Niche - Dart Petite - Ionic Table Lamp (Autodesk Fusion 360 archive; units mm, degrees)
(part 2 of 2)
sketch "Sketch4" plane through (0, 23.8125, 0) normal (0, 1, 0) x axis (-1, 0, 0)
  line L1 (-7.1437, -2.6987) -> (-7.1437, 2.6987)
  line L2 (5.8737, -3.9688) -> (-5.8737, -3.9688)
  line L3 (7.1437, 2.6987) -> (7.1437, -2.6987)
  line L4 (-5.8737, 3.9688) -> (5.8737, 3.9688)
  line L5 (-3.81, 6.604) -> (3.81, 6.604)
  line L6 (3.81, -6.604) -> (-3.81, -6.604)
  line L7 (-10.414, 0) -> (10.414, 0)
  arc A1 centre (-5.8737, 2.6987) radius 1.27 clockwise from (-7.1437, 2.6987) to (-5.8737, 3.9688)
  arc A2 centre (-5.8737, -2.6987) radius 1.27 clockwise from (-5.8737, -3.9688) to (-7.1437, -2.6987)
  arc A3 centre (5.8737, -2.6987) radius 1.27 clockwise from (7.1437, -2.6987) to (5.8737, -3.9688)
  arc A4 centre (5.8737, 2.6987) radius 1.27 clockwise from (5.8737, 3.9688) to (7.1437, 2.6987)
  arc A5 centre (-3.81, 0) radius 6.604 clockwise from (-3.81, -6.604) to (-3.81, 6.604)
  arc A6 centre (3.81, 0) radius 6.604 clockwise from (3.81, 6.604) to (3.81, -6.604)
  point P20 (10.414, 0)
  point P21 (-10.414, 0)
  tangent L5 A5
  tangent A5 L6
  parallel L5 L6
  tangent L6 A6
  tangent L5 A6
  midpoint A6 P20
  midpoint A5 P21
  perpendicular L1 L7
extrude "Extrude4" add sketch "Sketch4" profile of A1 L1 A2 L2 A3 L3 A4 L4 L5 A5 L6 A6 against normal blind 2.286
chamfer "Chamfer2" distance 1.778
fillet "Fillet3" radius 1.778
fillet "Fillet4" radius 0.254
fillet "Fillet5" radius 0.254
fillet "Fillet6" radius 0.254
fillet "Fillet7" radius 3.175
sketch "Sketch5" plane through (0, 0, 0) normal (0, -1, 0) x axis (1, 0, 0)
  line L1 (-13.2397, -5.715) -> (-13.2397, 5.715)
  line L2 (9.6837, -9.271) -> (-9.6837, -9.271)
  line L3 (13.2397, 5.715) -> (13.2397, -5.715)
  line L4 (-9.6837, 9.271) -> (9.6837, 9.271)
  line L5 (-6.35, -3.175) -> (-6.35, 3.175)
  line L6 (6.35, 3.175) -> (-6.35, -3.175)
  line L7 (-6.35, 3.175) -> (6.35, -3.175)
  line L8 (-4.7625, 3.175) -> (-6.35, 3.175)
  line L9 (-4.7625, -3.175) -> (-4.7625, 3.175)
  line L10 (-6.35, -3.175) -> (-4.7625, -3.175)
  line L11 (-6.35, 3.175) -> (-6.35, -3.175)
  line L12 (0, -3.302) -> (0, 3.81)
  line L13 (4.7625, -3.175) -> (4.7625, 3.175)
  line L14 (4.7625, 3.175) -> (6.35, 3.175)
  line L15 (6.35, -3.175) -> (6.35, 3.175)
  line L16 (6.35, -3.175) -> (4.7625, -3.175)
  arc A1 centre (-9.6837, 5.715) radius 3.556 clockwise from (-13.2397, 5.715) to (-9.6837, 9.271)
  arc A2 centre (-9.6837, -5.715) radius 3.556 clockwise from (-9.6837, -9.271) to (-13.2397, -5.715)
  arc A3 centre (9.6837, -5.715) radius 3.556 clockwise from (13.2397, -5.715) to (9.6837, -9.271)
  arc A4 centre (9.6837, 5.715) radius 3.556 clockwise from (9.6837, 9.271) to (13.2397, 5.715)
  point P18 (0, 0)
  point P1 (0, 0)
  point P14 (-6.35, -3.175)
  point P27 (6.35, -3.175)
  point P17 (-6.35, 3.175)
  point P26 (6.35, 3.175)
  point P19 (-4.7625, 3.175)
  point P24 (4.7625, 3.175)
  point P20 (-4.7625, -3.175)
  point P25 (4.7625, -3.175)
  point P21 (-6.35, -3.175)
  point P28 (6.35, -3.175)
  point P15 (6.35, -3.175)
  point P16 (6.35, 3.175)
  coincident L6 P18
  coincident L7 P18
  coincident P1 P18
  horizontal L8
  vertical L9
  horizontal L10
  vertical L11
  vertical L12
  symmetric P14 L12 P27
  symmetric P17 L12 P26
  symmetric P19 L12 P24
  symmetric P20 L12 P25
  symmetric P21 L12 P28
  dimension "d36" distance P15 P16 = 6.35
  dimension "d37" distance P17 P19 = 1.5875
extrude "Extrude5" add sketch "Sketch5" profile of L5 L8 L9 L10 L11 L13 L14 L15 L16 along normal blind 15.875
sketch "Sketch7" plane through (0, 0, 3.175) normal (0, 0, 1) x axis (-1, 0, 0)
  line L1 (-4.7625, 0) -> (-6.35, 0)
  line L2 (-4.7625, 15.875) -> (-4.7625, 0)
  line L3 (-6.35, 15.875) -> (-4.7625, 15.875)
  line L4 (-6.35, 0) -> (-6.35, 15.875)
  line L5 (-4.7625, 15.875) -> (-6.35, 15.875)
  line L6 (-4.7625, 9.525) -> (-4.7625, 15.875)
  line L7 (-6.35, 9.525) -> (-4.7625, 9.525)
  line L8 (-6.35, 15.875) -> (-6.35, 9.525)
  point P5 (-6.35, 15.875)
  point P6 (-6.35, 15.875)
  point P9 (-6.35, 9.525)
  horizontal L5
  vertical L6
  horizontal L7
  vertical L8
  coincident P5 P6
  dimension "d45" distance P6 P9 = 6.35
extrude "Extrude7" add sketch "Sketch7" profile of L2 L3 L4 L5 L6 L7 L8 against normal blind 7.9375 and along normal blind 1.5875
chamfer "Chamfer3" distance 0.508
chamfer "Chamfer4" distance 0.635 distance 0.635
sketch "Sketch6" plane through (6.35, 0, 0) normal (1, 0, 0) x axis (0, 1, 0)
  line L1 (0, -3.175) -> (-9.525, -3.175)
  line L2 (0, 3.175) -> (0, -3.175)
  line L3 (-9.525, 3.175) -> (0, 3.175)
  line L4 (-15.367, -4.6355) -> (-15.367, 4.6355)
  line L5 (-11.43, 0) -> (-16.002, 0)
  line L6 (-9.525, -4.7625) -> (-15.24, -4.7625)
  line L7 (-9.525, -3.175) -> (-9.525, -4.7625)
  line L8 (-9.525, 4.7625) -> (-9.525, 3.175)
  line L9 (-15.24, 4.7625) -> (-9.525, 4.7625)
  line L10 (-15.24, -4.7625) -> (-15.367, -4.6355)
  line L11 (-15.367, 4.6355) -> (-15.24, 4.7625)
  circle C1 centre (-11.43, 0) radius 1.5875
  point P9 (-11.43, 0)
  point P10 (-11.43, 0)
  perpendicular L4 L5
  coincident P9 P10
  dimension "d42" diameter C1 = 3.175
extrude "Extrude6" cut sketch "Sketch6" profile of C1 against normal blind 20.32
chamfer "Chamfer5" distance 3.175 distance 1.5875 distance 3.175 distance 1.5875
component_from_bodies "Body->Comp"
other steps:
base_feature "Base Feature" bodies "2-Pole Plug End"
create_component "CreateComponent1"
remove_body "RemoveBody1"
named bodies: "2-Pole Plug End"

design "Marble Base - Plastic Insert"
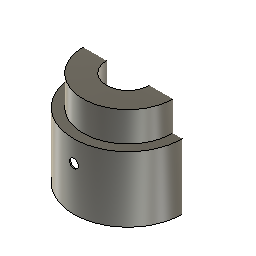
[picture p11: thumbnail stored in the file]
sketch "Sketch1" plane through (0, 0, 0) normal (0, 0, 1) x axis (1, 0, 0)
  circle C1 centre (0, 0) radius 50.038
  point P1 (0, 0)
  point P2 (0, 0)
  coincident P1 P2
  dimension "d1" diameter C1 = 100.076
extrude "Extrude1" new body sketch "Sketch1" along normal blind 72.898 bodies "Plastic Insert"
shell "Shell1" innerThickness 1.016
work_plane "WorkPlane1" AlongDistance 18.034
sketch "Sketch2" plane through (0, 0, 90.932) normal (0, 0, 1) x axis (1, 0, 0)
  circle C1 centre (0, 0) radius 20.701
  point P1 (0, 0)
  point P2 (0, 0)
  coincident P1 P2
  dimension "d6" diameter C1 = 41.402
extrude "Extrude2" add sketch "Sketch2" against normal blind 65.024
shell "Shell2" innerThickness 1.016
sketch "Sketch3" plane through (0, 0, 0) normal (0, 1, 0) x axis (1, 0, 0)
  line L1 (5.08, -20.32) -> (-5.08, -20.32)
  line L2 (5.08, 20.32) -> (5.08, -20.32)
  line L3 (-5.08, 20.32) -> (5.08, 20.32)
  line L4 (-5.08, -20.32) -> (-5.08, 20.32)
  line L5 (5.08, 20.32) -> (-5.08, -20.32)
  line L6 (-5.08, 20.32) -> (5.08, -20.32)
  point P6 (0, 0)
  point P1 (0, 0)
  horizontal L1
  perpendicular L1 L2
  parallel L1 L3
  parallel L2 L4
  coincident L5 P6
  coincident L6 P6
  coincident P1 P6
extrude "Extrude3" cut sketch "Sketch3" profile of L1 L2 L3 L4 along normal blind 91.44
sketch "Sketch4" plane through (0, 0, 0) normal (0, 1, 0) x axis (1, 0, 0)
  line L1 (0, -40.64) -> (0, 0)
  circle C1 centre (0, -40.64) radius 4.064
  point P1 (0, 0)
  point P2 (0, 0)
  point P3 (0, -40.64)
  point P4 (0, -40.64)
  coincident P1 P2
  vertical L1
  coincident P3 P4
  dimension "d12" diameter C1 = 8.128
work_plane "WorkPlane2" AlongDistance -91.44
sketch "Sketch5" plane through (0, -91.44, 0) normal (0, 1, 0) x axis (1, 0, 0)
  circle C1 centre (0, -40.64) radius 4.064
extrude "Extrude4" cut sketch "Sketch5" along normal blind 63.5
sketch "Sketch6" plane through (0, 0, 26.924) normal (0, 0, 1) x axis (-1, 0, 0)
  circle C1 centre (0, 0) radius 19.685
  circle C2 centre (0, 0) radius 5.461
  concentric C1 C2
  dimension "d16" diameter C2 = 10.922
extrude "Extrude5" cut sketch "Sketch6" profile of C2 against normal blind 15.24
sketch "Sketch7" plane through (0, 0, 72.898) normal (0, 0, 1) x axis (-1, 0, 0)
  circle C1 centre (0, 0) radius 20.701
  circle C2 centre (0, 0) radius 50.038
  circle C3 centre (0, 0) radius 20.701
  circle C4 centre (0, 0) radius 45.72
  point P1 (0, 0)
  point P3 (0, 0)
  point P4 (0, 0)
  coincident P1 P3
  coincident P1 P4
extrude "Extrude6" add sketch "Sketch7" profile of C1 C3 C4 along normal blind 18.034
sketch "Sketch8" plane through (0, 0, 71.882) normal (0, 0, -1) x axis (1, 0, 0)
  circle C1 centre (0, 0) radius 20.701
  circle C2 centre (0, 0) radius 49.022
  circle C3 centre (0, 0) radius 20.701
  circle C4 centre (0, 0) radius 44.704
  point P1 (0, 0)
  point P3 (0, 0)
  point P4 (0, 0)
  coincident P1 P3
  coincident P1 P4
  dimension "d21" diameter C4 = 89.408
extrude "Extrude7" cut sketch "Sketch8" profile of C1 C3 C4 against normal blind 17.78
extrude "Extrude8" add of existing geometry blind 9.398
extrude "Extrude9" cut of existing geometry blind -9.398
component_from_bodies "Body->Comp"
offset_faces "OffsetFaces1" distance 4.445
offset_faces "OffsetFaces2" distance -4.445
offset_faces "OffsetFaces3" distance 3.175
offset_faces "OffsetFaces4" distance 3.175
offset_faces "OffsetFaces5" distance 3.175
offset_faces "OffsetFaces6" distance -3.175
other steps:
base_feature "Base Feature" bodies "Plastic Insert"
create_component "CreateComponent1"
remove_body "RemoveBody1"
named bodies: "Plastic Insert"

design "Rubber Grommet"
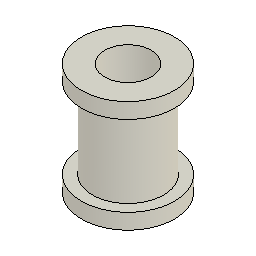
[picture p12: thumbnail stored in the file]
sketch "Sketch1" plane through (0, 0, 0) normal (0, 1, 0) x axis (1, 0, 0)
  line L1 (0, 3.048) -> (0, -12.7)
  line L2 (5.842, 0.508) -> (5.842, -12.7)
  line L3 (3.81, 3.048) -> (3.81, -15.24)
  line L4 (7.62, -12.7) -> (7.62, -15.24)
  line L5 (7.62, 3.048) -> (7.62, 0.508)
  line L6 (7.62, 0.508) -> (5.842, 0.508)
  line L7 (7.62, -12.7) -> (5.842, -12.7)
  line L8 (7.62, -15.24) -> (3.81, -15.24)
  line L9 (7.62, 3.048) -> (3.81, 3.048)
  vertical L1
  collinear L4 L5
revolve "Revolve1" sketch "Sketch1" AlongAngle 360 bodies "Rubber Grommet"
component_from_bodies "Body->Comp"
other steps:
base_feature "Base Feature" bodies "Rubber Grommet"
create_component "CreateComponent1"
remove_body "RemoveBody1"
named bodies: "Rubber Grommet"

design "Trove - TL"
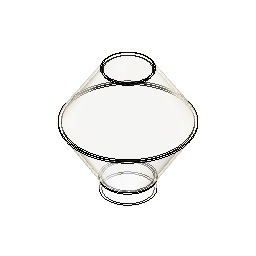
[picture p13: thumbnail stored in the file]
derived_base_feature "Derived Base Feature" bodies "Trove"
hole "Hole1" HoleDepth 88.9 HoleDiameter 44.45 TipAngle 118
sketch "Sketch1" plane through (0, 0, 0) normal (1, 0, 0) x axis (0, 1, 0)
  line L1 (0, 243.0601) -> (0, 247.8226)
  line L2 (-50.8, -12.7122) -> (-50.8, 10.9447)
  line L3 (0, -25.4) -> (0, 243.0601)
  line L4 (-46.0375, -12.7122) -> (-50.8, -12.7122)
  line L5 (-46.0375, -12.7122) -> (-46.0375, 12.3043)
  line L6 (-45.9716, 247.8226) -> (0, 247.8226)
  line L7 (-43.3841, 243.0601) -> (0, 243.0601)
  line L8 (-122.8321, 128.6352) -> (-51.757, 14.2971)
  line L9 (-117.1907, 128.5808) -> (-46.9945, 15.6567)
  line L10 (-48.6353, 246.3754) -> (-122.7993, 132.0392)
  line L11 (-46.0478, 241.6129) -> (-117.1579, 131.9848)
  arc A1 centre (-57.15, 10.9447) radius 6.35 clockwise from (-51.757, 14.2971) to (-50.8, 10.9447)
  arc A2 centre (-52.3875, 12.3043) radius 6.35 clockwise from (-46.9945, 15.6567) to (-46.0375, 12.3043)
  arc A3 centre (-114.4942, 130.257) radius 3.175 between (-117.1579, 131.9848) and (-117.1907, 128.5808)
  arc A4 centre (-120.1356, 130.3114) radius 3.175 between (-122.7993, 132.0392) and (-122.8321, 128.6352)
  arc A5 centre (-45.9716, 244.6476) radius 3.175 between (-45.9716, 247.8226) and (-48.6353, 246.3754)
  arc A6 centre (-43.3841, 239.8851) radius 3.175 clockwise from (-46.0478, 241.6129) to (-43.3841, 243.0601)
  point P3 (0, 247.8226)
  point P4 (0, 243.0601)
  vertical L1
  vertical L3
  tangent L5 A2
  perpendicular L1 L6
  perpendicular L1 L7
  tangent L11 A3
  tangent L9 A3
  tangent L10 A4
  tangent L8 A4
  equal A3 A4
  tangent L6 A5
  tangent L10 A5
  tangent L11 A6
  tangent L7 A6
  dimension "d8" distance P3 P4 = 4.7625
  dimension "d11" radius A2 = 6.35
  dimension "d15" radius A3 = 3.175
  dimension "d16" radius A5 = 3.175
  dimension "d17" radius A6 = 3.175
revolve "Revolve1" sketch "Sketch1" AlongAngle 180 bodies "Trove - TL"
revolve "Revolve2" sketch "Sketch1" AlongAngle -180
component_from_bodies "Body->Comp"
remove_body "RemoveBody2"
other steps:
base_feature "Base Feature" bodies "Trove - TL"
create_component "CreateComponent1"
remove_body "RemoveBody1"
named bodies: "Trove", "Trove - TL"

design "T9-5In"
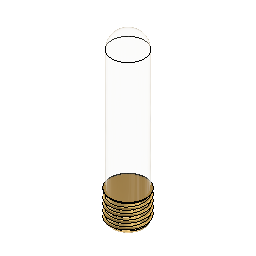
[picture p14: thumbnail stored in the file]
sketch "Sketch1" plane through (0, 0, 0) normal (0, 1, 0) x axis (1, 0, 0)
  line L1 (0, 0) -> (0, -127)
  line L2 (12.7, -127) -> (-12.7, -127)
  line L3 (12.7, -12.7) -> (12.7, -127)
  line L4 (-12.7, -127) -> (-12.7, -12.7)
  arc A1 centre (0, -12.7) radius 12.7 clockwise from (-12.7, -12.7) to (12.7, -12.7)
  point P1 (0, 0)
  point P3 (0, 0)
  coincident P1 P3
  vertical L1
  horizontal L2
  vertical L3
  vertical L4
revolve "Revolve1" sketch "Sketch1" AlongAngle 360 bodies "BU-T10-5-LED-120V"
derived_base_feature "Derived Base Feature" bodies "E26 Base"
move "Move1"
component_from_bodies "Body->Comp"
copy_paste "CutPaste"
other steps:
base_feature "Base Feature" bodies "BU-T10-5-LED-120V"
create_component "CreateComponent1"
create_component "CreateComponent2"
remove_body "RemoveBody1"
remove_instance "RemoveInstance1"
named bodies: "BU-T10-5-LED-120V", "E26 Base"

design "Orb 8.5In - Solitaire Petite"
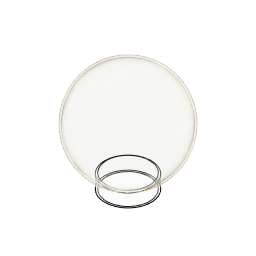
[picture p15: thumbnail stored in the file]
sketch "Sketch1" plane through (0, 0, 0) normal (0, 1, 0) x axis (1, 0, 0)
  line L1 (0, 190.5) -> (0, -127)
  line L2 (50.8, 190.5) -> (50.8, -127)
  line L3 (-50.8, 190.5) -> (-50.8, -127)
  line L4 (50.8, 95.25) -> (-50.8, 95.25)
  line L5 (50.8, 123.825) -> (-50.8, 123.825)
  line L6 (101.6, -107.95) -> (0, -107.95)
  circle C1 centre (0, 0) radius 107.95
  point P1 (0, 0)
  point P2 (0, 0)
  point P5 (50.8, -127)
  point P7 (-50.8, -127)
  point P6 (50.8, 190.5)
  point P8 (-50.8, 190.5)
  point P9 (-50.8, 95.25)
  point P10 (50.8, 95.25)
  point P13 (0, -107.95)
  coincident P1 P2
  vertical L1
  symmetric L1 P5 P7
  symmetric L1 P6 P8
  coincident C1 P9
  coincident L3 P9
  coincident C1 P10
  coincident L2 P10
  perpendicular L2 L4
  coincident C1 P13
  coincident L1 P13
  tangent C1 L6
  dimension "d1" diameter C1 = 215.9
  dimension "d2" = 50.8
  dimension "d4" = -28.575
revolve "Revolve1" sketch "Sketch1" AlongAngle 360 bodies "Orb-8.5"
shell "Shell1" innerThickness 3.81
component_from_bodies "Body->Comp"
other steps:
base_feature "Base Feature" bodies "Orb-8.5"
create_component "CreateComponent1"
remove_body "RemoveBody1"
named bodies: "Orb-8.5"

design "Dart"
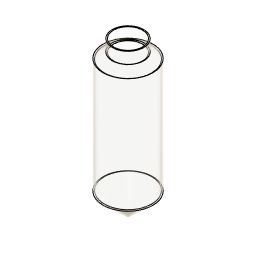
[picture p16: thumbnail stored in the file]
sketch "Sketch1" plane through (0, 0, 0) normal (0, 0, 1) x axis (1, 0, 0)
work_plane "WorkPlane1" AlongDistance 76.2
sketch "Sketch2" plane through (0, 0, 76.2) normal (0, 0, 1) x axis (1, 0, 0)
sketch "Sketch3" plane through (0, 0, 76.2) normal (0, 0, 1) x axis (1, 0, 0)
sketch "Sketch4" plane through (0, 0, 76.2) normal (0, 0, 1) x axis (1, 0, 0)
  circle C1 centre (0, 0) radius 82.55
  point P1 (0, 0)
  point P2 (0, 0)
  coincident P1 P2
  dimension "d2" diameter C1 = 165.1
loft "Loft1" sketch "Sketch4" bodies "Dart Grand"
extrude "Extrude1" add of existing geometry blind 381
work_plane "WorkPlane2" AlongDistance 19.05
sketch "Sketch5" plane through (0, 0, 476.25) normal (0, 0, 1) x axis (1, 0, 0)
  circle C1 centre (0, 0) radius 52.07
  point P1 (0, 0)
  point P2 (0, 0)
  coincident P1 P2
  dimension "d6" diameter C1 = 104.14
loft "Loft2" sketch "Sketch5"
extrude "Extrude2" add of existing geometry blind 38.1
shell "Shell3" innerThickness 3.81
component_from_bodies "Body->Comp"
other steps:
base_feature "Base Feature" bodies "Dart Grand"
create_component "CreateComponent1"
remove_body "RemoveBody1"
named bodies: "Dart Grand"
